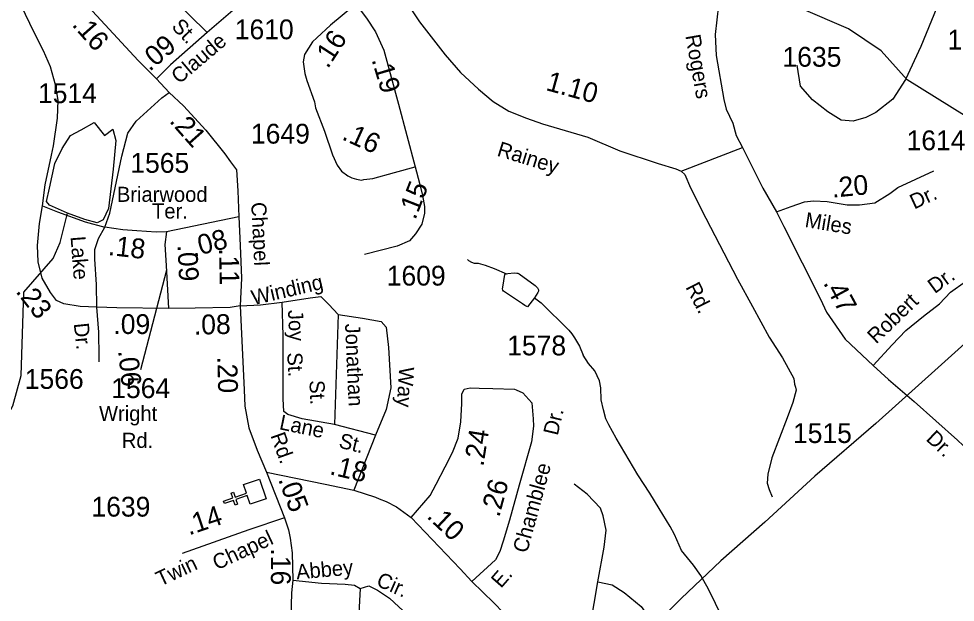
# Model space of a CAD drawing. Extents: x 1473865 to 1648260, y 639067 to 773536.
# Drawn here: x 1534546 to 1540456, y 693485 to 697165 of the extents above; entities that cross this region are included whole.
import ezdxf

# ---------------------------------------------------------------- set-up
doc = ezdxf.new("R2010")
doc.units = 0
for name, color, linetype in [('Exist Cultural Church CELL', 7, 'Continuous'), ('Exist Hydrographic Creek Single Shore', 7, 'Continuous'), ('Exist Hydrographic Misc Water Feature', 7, 'Continuous'), ('Exist Road Non-System Type 51', 7, 'Continuous'), ('Exist Road Non-System Type 51 Label', 7, 'Continuous'), ('Exist Road Secondary Mileage Hundredths English Label', 7, 'Continuous'), ('Exist Road Secondary Type 41 Attributed', 7, 'Continuous'), ('Exist Road Secondary Type 51 Attributed', 7, 'Continuous'), ('Exist Road Secondary Type 51 Label', 7, 'Continuous'), ('Exist Road Secondary Type 51 Number Label', 7, 'Continuous'), ('Exist Utilities Electrical Transmission Line', 7, 'Continuous')]:
    doc.layers.add(name, color=color, linetype=linetype)

msp = doc.modelspace()

# ---------------------------------------------------------------- linework, layer by layer
at = {"layer": 'Exist Cultural Church CELL'}
msp.add_lwpolyline([(1536007.1, 694103.4), (1535988.7, 694157.3), (1535916.6, 694132.7), (1535926.9, 694102.4), (1535911.8, 694097.2), (1535901.5, 694127.5), (1535844.5, 694108.1), (1535839.4, 694123.3), (1535896.3, 694142.7), (1535886, 694173), (1535901.1, 694178.1), (1535911.4, 694147.8), (1535983.5, 694172.4), (1535965, 694227), (1536065.7, 694261.4), (1536107.9, 694137.8)], close=True, dxfattribs=at)
at = {"layer": 'Exist Hydrographic Creek Single Shore'}
msp.add_lwpolyline([(1537498.9, 689765.2), (1537012.2, 690038.3), (1536449.8, 690392.6), (1535754.4, 690742.8), (1535507.4, 690898.7), (1534940.4, 691415.6), (1534630.4, 691904.5), (1534477.4, 692222.7), (1534310.4, 692718.4), (1534277.4, 692768.3), (1534050.4, 693705.1), (1534085.5, 693806.1), (1534204.4, 693944.9), (1534247.5, 694052.3), (1534276.5, 694301.2), (1534508.5, 694723.3), (1534561.5, 694915.9), (1534578.4, 695440.8), (1534764.5, 695653.6), (1534808.5, 695754.5), (1534853.6, 695939.4)], dxfattribs=at)
at = {"layer": 'Exist Hydrographic Misc Water Feature'}
for points in [[(1542137.6, 693728.9), (1541965.5, 693939.2), (1541887.6, 694232.9), (1541732.6, 694492.1), (1541485.6, 695173.3), (1541389.5, 695441.1), (1541300.5, 695600.5), (1541037.6, 695861.8), (1540915.6, 696048.1), (1540750.6, 696149.9), (1540701.6, 696210), (1540645.6, 696385.1), (1540514.6, 696555.1), (1540151.5, 696779.1), (1539987.6, 696963), (1539781.5, 697101.7), (1539185.5, 697359.9), (1538731.5, 697658), (1537891.5, 698288.7), (1537650.5, 698369.1), (1537533.5, 698368.2)], [(1534853.6, 695939.4), (1534741.1, 695990), (1534722, 696011.3), (1534741.1, 696096.2), (1534775.1, 696251.1), (1534819.6, 696346.6), (1534872.6, 696429.4), (1534940.5, 696463.4), (1535023.2, 696510.1), (1535086.8, 696429.4), (1535139.9, 696467.6), (1535158.9, 696397.6), (1535142, 696217.1), (1535112.3, 695968.8), (1535078.3, 695896.6), (1535040.2, 695877.5), (1534963.8, 695898.8), (1534853.6, 695939.4)], [(1537377.1, 695647.4), (1537384.9, 695641.2), (1537402.6, 695630.7), (1537420.4, 695624.3), (1537444.5, 695623.7), (1537460.4, 695619.3), (1537490.2, 695610.5), (1537545.6, 695589.2), (1537623.6, 695556.6)], [(1537800.9, 695404.8), (1537757.5, 695347.6), (1537740.6, 695356.3), (1537724.5, 695366.9), (1537604.2, 695446.5), (1537601, 695452.4), (1537599.8, 695461.1), (1537600.4, 695472.4), (1537614.4, 695551.6), (1537616.6, 695555.2), (1537623.6, 695556.6)], [(1537623.6, 695556.6), (1537632.4, 695558.5), (1537672.8, 695561.5), (1537689.1, 695561.2), (1537695.9, 695559.9), (1537703.8, 695555.4), (1537805.8, 695481.6), (1537811.9, 695477.2), (1537819.7, 695467.2), (1537827.1, 695454.6), (1537825.8, 695447.4), (1537820.9, 695438.1), (1537800.9, 695404.8)], [(1537800.9, 695404.8), (1537842, 695373.7), (1538017.4, 695200.6), (1538035.6, 695178.4), (1538053.5, 695152.3), (1538084.8, 695100.4), (1538107.2, 695044.1)], [(1538987.1, 693387), (1538898.7, 693566.7), (1538850.3, 693653.7), (1538803.5, 693718.6), (1538729.4, 693812), (1538685.3, 693912.9), (1538657.9, 693961.7), (1538588.4, 694076.7), (1538528.3, 694171.9), (1538452.6, 694287.4), (1538317, 694520.1), (1538270.6, 694603), (1538251.4, 694641.4), (1538236.4, 694697.6), (1538221.7, 694761.9), (1538219.2, 694837.9), (1538212, 694882), (1538181.9, 694944), (1538142.1, 694991.4), (1538107.2, 695044.1)]]:
    msp.add_lwpolyline(points, dxfattribs=at)
at = {"layer": 'Exist Road Non-System Type 51'}
for p, q in [((1538727.3, 696203.6), (1539112.4, 696353.4)), ((1535054.7, 695000.3), (1535054.7, 695033.6))]:
    msp.add_line(p, q, dxfattribs=at)
for points in [[(1534753.1, 696303.9), (1534765.5, 696362.9), (1534789.9, 696538.7), (1534795.3, 696650.6), (1534778.5, 696748.8), (1534746.1, 696861.3), (1534703.4, 696962), (1534643.1, 697078.9), (1534561.3, 697248.2), (1534549.9, 697290.3), (1534556.4, 697332.4)], [(1535090.5, 695850), (1535121.7, 695937.7), (1535196.6, 696298.7), (1535234.5, 696442.4), (1535287.5, 696519.6), (1535449.5, 696665.4), (1535496.1, 696699.5)], [(1534696.4, 695985.5), (1534789.9, 695946.2), (1534965.1, 695883.8), (1535090.5, 695850)], [(1539938.9, 694977.3), (1540057.2, 695107.4), (1540143.8, 695198.1), (1540255, 695288.8), (1540356, 695367.2), (1540426.1, 695439.6), (1540520.7, 695508.7)], [(1536208.2, 695378.1), (1536386.3, 695404.4), (1536453.5, 695413.1), (1536503.1, 695363.4), (1536561.5, 695299.2)], [(1535943.4, 695354), (1536071, 695360.5), (1536208.2, 695378.1)], [(1536538.1, 694606.8), (1536333.8, 694641.8), (1536243.3, 694668.1), (1536219.9, 694688.6), (1536214.1, 694767.4), (1536214.1, 695167.7), (1536208.2, 695378.1)], [(1536561.5, 695299.2), (1536538.1, 694606.8)], [(1536561.5, 695299.2), (1536716.2, 695275.8), (1536833, 695255.3), (1536865.1, 695220.3), (1536879.7, 695091.7), (1536894.3, 694837.6), (1536865.1, 694700.2), (1536798, 694539.6)], [(1539451.9, 694821.5), (1539430.6, 694744.4), (1539394.2, 694648.3), (1539299.4, 694394.6), (1539272.9, 694292.6), (1539268.8, 694234.9), (1539281.2, 694195.7), (1539299.7, 694150.3)], [(1536798, 694539.6), (1536538.1, 694606.8)], [(1536798, 694539.6), (1536660.7, 694191.9)], [(1538200.4, 693613.6), (1538240.3, 693833.1), (1538253.6, 693939.5), (1538233.7, 694029.3), (1538217.1, 694079.2), (1538134, 694165.6), (1538050.9, 694228.8)], [(1536276.6, 693624.9), (1536457.3, 693605.3), (1536605.2, 693598.1), (1536664.3, 693592.8), (1536700.8, 693571)], [(1536700.8, 693571), (1536664.6, 692913.1), (1536653.8, 692721), (1536628.6, 692596.4)], [(1536700.8, 693571), (1536755, 693587.3), (1536810.9, 693560.2), (1536886.7, 693511.4), (1537002.1, 693403.1)], [(1538011, 693008.3), (1538090.8, 693131.3), (1538153.9, 693340.8), (1538200.4, 693613.6)], [(1538200.4, 693613.6), (1538290.2, 693593.6), (1538366.6, 693547), (1538473, 693457.2), (1538595.9, 693287.6), (1538795.3, 693034.9)]]:
    msp.add_lwpolyline(points, dxfattribs=at)
at = {"layer": 'Exist Road Secondary Type 41 Attributed'}
msp.add_lwpolyline([(1537013.1, 697239.8), (1537074.2, 697145.1), (1537236.3, 696937.3), (1537333.1, 696826.3), (1537448.3, 696721.1), (1537539.4, 696644), (1537638.8, 696583), (1537751.2, 696538.7), (1537852.2, 696501.6), (1538137.3, 696417.8), (1538340, 696332.8), (1538581.8, 696253), (1538693.5, 696217.9), (1538727.3, 696203.6), (1538749.4, 696182.9), (1538785.7, 696098.6), (1538881.3, 695906.4), (1539081.3, 695521.7), (1539176.1, 695350.5), (1539280.6, 695156.5), (1539365.2, 695025.5), (1539436.8, 694895.4), (1539441.6, 694860.7), (1539447.8, 694842.1), (1539451.9, 694821.5)], dxfattribs=at)
at = {"layer": 'Exist Road Secondary Type 51 Attributed'}
for p, q in [((1535735.4, 697078.9), (1535482.6, 697326.3)), ((1535935.1, 695914.8), (1535479.3, 695821.9)), ((1536110, 694304.5), (1536223.8, 694016.8))]:
    msp.add_line(p, q, dxfattribs=at)
for points in [[(1538978.7, 699206.2), (1538979.1, 699070.4), (1538973.3, 698696.3), (1538973.8, 698336.1), (1538968, 697938.1), (1538967.1, 697419.8), (1538961.5, 697251.6), (1538941.6, 697065.7), (1538946.3, 696933.8), (1538995.7, 696655), (1539009.4, 696594.7), (1539052.6, 696506), (1539073.2, 696427.7), (1539112.4, 696353.4), (1539162.2, 696256.1), (1539242.2, 696095.6), (1539328.1, 695947.6)], [(1540617.8, 698062.3), (1540517.5, 697586.1), (1540452.4, 697440.4), (1540340.2, 697235.9), (1540238.8, 696990.1), (1540142.6, 696781.7), (1540062.5, 696658.7), (1539955.7, 696573.2), (1539891.6, 696541.2), (1539811.5, 696519.8), (1539736.8, 696525.1), (1539651.3, 696578.6), (1539555.2, 696653.4), (1539480.4, 696738.9), (1539459.1, 696872.5)], [(1534828.4, 697412.6), (1535299.3, 696901), (1535416, 696787)], [(1536054.8, 697354.1), (1535940.9, 697254), (1535735.4, 697078.9)], [(1536674.4, 697257), (1536514.3, 697123.4), (1536428.2, 697045), (1536401, 697018.7), (1536348.7, 696939), (1536340.9, 696892.7), (1536351.1, 696819), (1536363.7, 696776.5), (1536412.2, 696641.3), (1536418.8, 696602.3)], [(1536674.4, 697257), (1536741.7, 697168.7), (1536798, 697081.5), (1536849.9, 696966.7), (1536942.1, 696625.5), (1537047.6, 696231.3)], [(1535735.4, 697078.9), (1535503.6, 696874), (1535416, 696787)], [(1535416, 696787), (1535496.1, 696699.5), (1535585, 696616.1), (1535726.6, 696463.2), (1535846.1, 696313.1), (1535882.2, 696263.1), (1535919.7, 696211.8), (1535929.8, 696079.5), (1535935.1, 695914.8)], [(1536418.8, 696602.3), (1536476.7, 696455.5), (1536525.3, 696307.5), (1536556.2, 696241.3), (1536583.8, 696203.7), (1536622.5, 696173.9), (1536648.1, 696162.6), (1536676.6, 696153.1), (1536709.6, 696147.6), (1536723, 696151.8), (1536779.7, 696157.1), (1536918.4, 696194.9), (1537047.6, 696231.3)], [(1535039.9, 695346.4), (1534933.9, 695349.8), (1534830.2, 695367.3), (1534784.4, 695388), (1534747, 695438.6), (1534694.2, 695529.3), (1534669.7, 695631.6), (1534664.9, 695733.8), (1534677, 695873.8), (1534696.4, 695985.5), (1534714.1, 696117.4), (1534753.1, 696303.9)], [(1537047.6, 696231.3), (1537075.2, 696128.6), (1537094.9, 696050.5), (1537105.9, 695980.4), (1537106.9, 695938.3), (1537089.9, 695870.2), (1537050.9, 695808.1), (1537012.8, 695765.1), (1536934.7, 695730), (1536728.4, 695677)], [(1539328.1, 695947.6), (1539420.6, 695980.8), (1539504.9, 696010.1), (1539561.7, 696016.9), (1539647.7, 696012), (1539773.8, 695991.1), (1539851.6, 695990.3), (1539948.3, 696003.3), (1540044, 696062), (1540094.5, 696101.4), (1540320.9, 696206.5)], [(1539328.1, 695947.6), (1539373.9, 695854.6), (1539605.6, 695396.1), (1539643.6, 695314.9), (1539762.1, 695144.3), (1539938.9, 694977.3), (1540034.2, 694890.3), (1540196.9, 694751.2), (1540471.1, 694506.5), (1540542.2, 694438.8), (1540653.4, 694297.9), (1540730.1, 694197.8), (1540826.9, 694062.3)], [(1535935.1, 695914.8), (1535943.4, 695734.1), (1535951.8, 695529.1), (1535943.4, 695354)], [(1535039.9, 695346.4), (1535037.8, 695488.5), (1535025.8, 695648.9), (1535026.6, 695708.9), (1535049.6, 695778.4), (1535090.5, 695850)], [(1535479.3, 695821.9), (1535412.7, 695819.1), (1535290.5, 695827.5), (1535202.4, 695834.4), (1535090.5, 695850)], [(1535479.3, 695821.9), (1535468.2, 695741.3), (1535476.5, 695607.9), (1535490.4, 695338.2)], [(1535490.4, 695338.2), (1535165.8, 695340.7), (1535039.9, 695346.4)], [(1535054.7, 695033.6), (1535051.7, 695188.1), (1535039.9, 695346.4)], [(1535943.4, 695354), (1535879.9, 695344.7), (1535659.7, 695339.7), (1535490.4, 695338.2)], [(1535943.4, 695354), (1535968.3, 694824.3), (1535973.9, 694721.5), (1535998.9, 694585.3), (1536051.6, 694443.5), (1536110, 694304.5)], [(1537023.1, 694018.3), (1537142.8, 694158.4), (1537181.1, 694229.5), (1537237.6, 694339), (1537283.1, 694430.2), (1537319.6, 694519.6), (1537336, 694623.6), (1537343.3, 694737.8), (1537341.5, 694796.9), (1537357.9, 694829.7), (1537394.3, 694837), (1537452.7, 694835.2), (1537536.9, 694833.4), (1537674.2, 694829.7), (1537686.1, 694824.7)], [(1537686.1, 694824.7), (1537727.9, 694806), (1537784.4, 694742.1), (1537791.7, 694641.8), (1537793.5, 694596.2), (1537782.6, 694495.9), (1537704.2, 694224), (1537644, 694002.5), (1537602.1, 693869.3), (1537582.1, 693805.5), (1537554.7, 693752.6), (1537405.3, 693615.7)], [(1536110, 694304.5), (1536480.3, 694230.2), (1536660.7, 694191.9), (1536797, 694147.3), (1536821.5, 694137.5), (1536864.6, 694120.2), (1536930.8, 694086.4), (1537023.1, 694018.3)], [(1536223.8, 694016.8), (1535998.7, 693942), (1535577.2, 693793.1)], [(1536223.8, 694016.8), (1536248.7, 693941.5), (1536259.8, 693889.3), (1536271, 693797.2), (1536276.6, 693624.9), (1536268.3, 693544.2), (1536262.7, 693385.8), (1536232.6, 693234.8)], [(1537023.1, 694018.3), (1537332.3, 693694.7), (1537405.3, 693615.7)], [(1537405.3, 693615.7), (1537545.1, 693481.3), (1537728.1, 693292.3), (1538011, 693008.3), (1538187.2, 692828.8), (1538547.6, 692462.9), (1538732.9, 692284.1), (1538851.1, 692164.1), (1539033.5, 691972.6)]]:
    msp.add_lwpolyline(points, dxfattribs=at)
at = {"layer": 'Exist Road Secondary Type 51 Number Label'}
msp.add_line((1535479.2, 695578.7), (1535314.3, 694949.6), dxfattribs=at)
at = {"layer": 'Exist Utilities Electrical Transmission Line'}
msp.add_lwpolyline([(1540708, 695288.4), (1540348.4, 694964.3), (1539954.5, 694612.8), (1539568.8, 694279.3), (1539253.8, 693990.7), (1538975.7, 693745.2), (1538725.6, 693507.5), (1538351.3, 693137.7), (1537997.5, 692799.4), (1537647.8, 692465.3), (1537202.3, 692024.7), (1536828.2, 691663), (1536655.4, 691499.8), (1536594.3, 691438.8), (1536549.9, 691415.5), (1536401.1, 691370.1), (1536308.4, 691209.7), (1536195.2, 691025.5), (1536076.5, 690867.4), (1535909.1, 690662.3), (1535749.9, 690476.8), (1535554.1, 690252), (1535364.3, 690033.2), (1535240.1, 689897.2)], dxfattribs=at)

# ---------------------------------------------------------------- texts
at = {"layer": 'Exist Road Non-System Type 51 Label'}
for s, rotation, p in [('Winding', 13.16425, (1536027, 695357.8)), ('Dr.', 36.14459, (1540326.3, 695427.6)), ('Robert', 43.84298, (1539956.3, 695110.3)), ('Joy', 273.02955, (1536244.5, 695326.7)), ('Jonathan', 272.50515, (1536605, 695240.7)), ('St.', 273.02955, (1536240.1, 695058.6)), ('Way', 266.58278, (1536947, 694971.3)), ('St.', 272.50515, (1536380.2, 694883.5)), ('Lane', 348.31106, (1536186, 694576.3)), ('St.', 346.0077, (1536560.7, 694461.4)), ('Abbey', 4.95467, (1536300.4, 693628.4)), ('Cir.', 336.27186, (1536795.9, 693591.9))]:
    msp.add_text(s, height=95, rotation=rotation, dxfattribs=at).set_placement(p)
at = {"layer": 'Exist Road Secondary Mileage Hundredths English Label'}
for s, rotation, p in [('.16', 311.48288, (1534877.9, 697124.8)), ('.09', 40.26343, (1535371.9, 696828.6)), ('.16', 57.15405, (1536496.4, 696845.3)), ('.19', 286.67663, (1536771.9, 696906.9)), ('1.10', 344.56923, (1537867.2, 696715.9)), ('.21', 311.60968, (1535492.5, 696517.2)), ('.16', 335.57373, (1536579.5, 696406.2)), ('.20', 5.53881, (1539680.6, 696036.1)), ('.15', 68.64149, (1537048.5, 695892.1)), ('.08', 14.81718, (1535648.7, 695662.1)), ('.18', 353.52621, (1535107.1, 695675.6)), ('.09', 272.77783, (1535547.7, 695737.6)), ('.11', 271.19372, (1535810.2, 695716.5)), ('.23', 308.15529, (1534523.1, 695443.3)), ('.47', 298.43576, (1539620.4, 695499.2)), ('.09', 359.8644, (1535143.5, 695176.9)), ('.08', 1.28962, (1535652.6, 695172.4)), ('.06', 276.03656, (1535173.2, 695071)), ('.20', 271.65584, (1535798.9, 695033.9)), ('.24', 81.03519, (1537478, 694337.2)), ('.18', 346.80384, (1536502.8, 694292.5)), ('.05', 290.22296, (1536182.1, 694260)), ('.26', 74.81074, (1537577.8, 694016.5)), ('.14', 18.75716, (1535620.8, 693905.7)), ('.10', 316.84201, (1537115.8, 694021.7)), ('.16', 269.81933, (1536138.4, 693824.7))]:
    msp.add_text(s, height=125, rotation=rotation, dxfattribs=at).set_placement(p)
at = {"layer": 'Exist Road Secondary Type 51 Label'}
for s, rotation, p in [('St.', 314.17096, (1535505.2, 697110.7)), ('Claude', 40.26343, (1535558.6, 696749.5)), ('Rogers', 280.04922, (1538752.5, 697057.9)), ('Rainey', 342.88236, (1537559, 696302)), ('Dr.', 24.90339, (1540196.9, 695961.3)), ('Chapel', 272.779, (1536013, 696006.5)), ('Miles', 350.61688, (1539502.5, 695852.2)), ('Lake', 274.26939, (1534873.3, 695790.4)), ('Rd.', 296.9583, (1538751.7, 695472.6)), ('Dr.', 276.03656, (1534893.2, 695242.2)), ('Dr.', 76.62496, (1537947, 694532.2)), ('Rd.', 289.6068, (1536133.4, 694536.8)), ('Dr.', 316.80473, (1540266.3, 694509.6)), ('Chamblee', 74.70411, (1537753.7, 693790.1)), ('Chapel', 25.05754, (1535796.8, 693685.4)), ('Twin', 25.05754, (1535439.8, 693582.7)), ('E.', 48.71391, (1537589.1, 693568.9))]:
    msp.add_text(s, height=95, rotation=rotation, dxfattribs=at).set_placement(p)
for s, p in [('Briarwood', (1535165.7, 696010.1)), ('Ter.', (1535387.4, 695904.7)), ('Wright', (1535052.9, 694628)), ('Rd.', (1535196.9, 694458.5))]:
    msp.add_text(s, height=95, dxfattribs=at).set_placement(p)
at = {"layer": 'Exist Road Secondary Type 51 Number Label'}
for s, p in [('1610', (1535909.4, 697035.5)), ('1607', (1540406.9, 696970.9)), ('1635', (1539365.6, 696862.4)), ('1514', (1534667.8, 696632.6)), ('1649', (1536011.4, 696377.4)), ('1614', (1540148.7, 696335.6)), ('1565', (1535250.2, 696193.3)), ('1609', (1536868.4, 695482)), ('1578', (1537628.4, 695041.9)), ('1566', (1534584.4, 694830.5)), ('1564', (1535130.1, 694772.6)), ('1515', (1539431.8, 694489.2)), ('1639', (1535005.1, 694025))]:
    msp.add_text(s, height=125, dxfattribs=at).set_placement(p)

doc.saveas('drawing.dxf')
